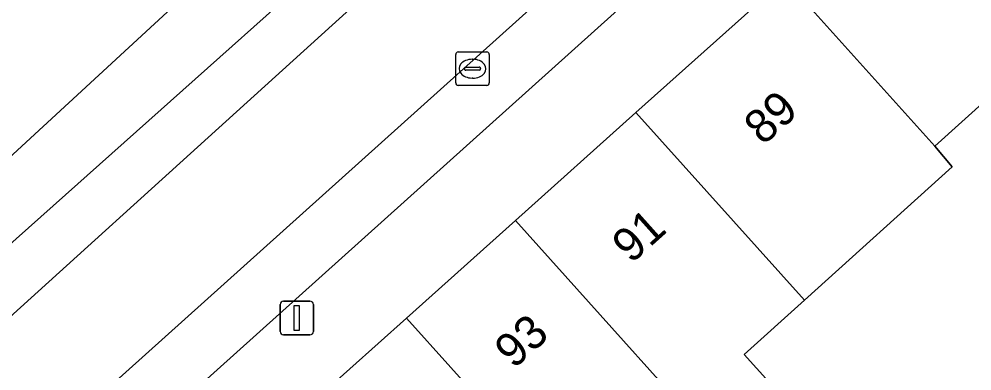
# Model space of a CAD drawing. Extents: x 162172 to 163187, y 382874 to 383685.
# Drawn here: x 162755.23 to 162783.66, y 383317.62 to 383328.11 of the extents above; entities that cross this region are included whole.
import ezdxf

# ---------------------------------------------------------------- set-up
doc = ezdxf.new("R2010")
doc.units = 0
for name, color, linetype in [('IMGEO_Berm_groen', 7, 'Continuous'), ('IMGEO_Erf', 7, 'Continuous'), ('IMGEO_Kolk', 7, 'Continuous'), ('IMGEO_Lichtmast', 7, 'Continuous'), ('IMGEO_Pand', 7, 'Continuous'), ('IMGEO_Pand_nummerreeks', 7, 'Continuous'), ('IMGEO_Parkeervlak_open', 7, 'Continuous'), ('IMGEO_Rijbaan_lokaal_open', 7, 'Continuous'), ('IMGEO_Voetpad_halfverhard', 7, 'Continuous'), ('IMGEO_Voetpad_open', 7, 'Continuous')]:
    doc.layers.add(name, color=color, linetype=linetype)

msp = doc.modelspace()

# ---------------------------------------------------------------- linework, layer by layer
at = {"layer": 'IMGEO_Berm_groen'}
for points in [[(162744.611, 383310), (162750.185, 383314.921), (162765.945, 383329.187), (162788.183, 383349.104), (162785.604, 383352.953), (162793.329, 383359.988), (162800.361, 383366.393), (162802.051, 383364.873), (162802.602, 383364.378)], [(162752.484, 383321.73), (162768.734, 383336.704)], [(162770.061, 383334.875), (162753.755, 383320.332)]]:
    msp.add_lwpolyline(points, dxfattribs=at)
at = {"layer": 'IMGEO_Erf'}
msp.add_lwpolyline([(162789.669, 383316.528), (162794.092, 383320.435), (162788.223, 383327.136), (162786.811, 383325.865), (162785.681, 383327.136), (162782.559, 383324.327), (162783.078, 383323.703), (162778.663, 383319.729), (162776.869, 383318.115), (162779.073, 383315.667)], dxfattribs=at)
at = {"layer": 'IMGEO_Kolk'}
for p, q in [((162768.26, 383326.208), (162768.26, 383327.06)), ((162768.335, 383327.134), (162769.187, 383327.134)), ((162769.261, 383327.06), (162769.261, 383326.208)), ((162768.748, 383326.914), (162768.773, 383326.914)), ((162768.519, 383326.628), (162768.519, 383326.64)), ((162768.957, 383326.591), (162768.559, 383326.591)), ((162768.562, 383326.677), (162768.96, 383326.677)), ((162769.003, 383326.64), (162769.003, 383326.628)), ((162768.771, 383326.354), (162768.746, 383326.354)), ((162769.187, 383326.134), (162768.335, 383326.134))]:
    msp.add_line(p, q, dxfattribs=at)
for points in [[(162768.26, 383326.208), (162768.26, 383327.06)], [(162768.335, 383327.134), (162769.187, 383327.134)], [(162769.261, 383327.06), (162769.261, 383326.208)], [(162769.187, 383326.134), (162768.335, 383326.134)]]:
    msp.add_lwpolyline(points, dxfattribs=at)
for centre, radius, start, end in [((162768.337, 383327.058), 0.0765, 91.552, 178.448), ((162768.337, 383327.058), 0.0765, 91.552, 178.448), ((162769.185, 383327.058), 0.0765, 1.552, 88.448), ((162769.185, 383327.058), 0.0765, 1.552, 88.448), ((162768.559, 383326.637), 0.0403, 85.8775, 175.7526), ((162768.556, 383326.627), 0.0366, 178.938, 274.7102), ((162768.96, 383326.634), 0.043, 264.8664, 352.4533), ((162768.964, 383326.639), 0.0386, 1.7309, 96.639), ((162768.337, 383326.21), 0.0765, 181.552, 268.448), ((162768.337, 383326.21), 0.0765, 181.552, 268.448), ((162769.185, 383326.21), 0.0765, 271.552, 358.448), ((162769.185, 383326.21), 0.0765, 271.552, 358.448)]:
    msp.add_arc(centre, radius, start, end, dxfattribs=at)
for centre, major_axis, ratio, start_param, end_param in [((162768.747, 383326.634), (-0.387, 0.002), 0.722429, 4.712389, 7.853982), ((162768.772, 383326.634), (-0.39, 0.002), 0.717154, 1.570796, 4.712389)]:
    msp.add_ellipse(centre, major_axis=major_axis, ratio=ratio, start_param=start_param, end_param=end_param, dxfattribs=at)
at = {"layer": 'IMGEO_Lichtmast'}
for p, q in [((162763.121, 383319.698), (162763.911, 383319.698)), ((162763.911, 383319.698), (162763.121, 383319.698)), ((162763.021, 383318.798), (162763.021, 383319.598)), ((162763.021, 383319.598), (162763.021, 383318.798)), ((162764.011, 383319.598), (162764.011, 383318.798)), ((162764.011, 383318.798), (162764.011, 383319.598)), ((162763.911, 383318.698), (162763.121, 383318.698)), ((162763.121, 383318.698), (162763.911, 383318.698))]:
    msp.add_line(p, q, dxfattribs=at)
msp.add_lwpolyline([(162763.441, 383319.573), (162763.591, 383319.573), (162763.591, 383318.823), (162763.441, 383318.823), (162763.441, 383319.573)], dxfattribs=at)
for centre, start, end in [((162763.121, 383319.598), 90, 180), ((162763.121, 383319.598), 90, 180), ((162763.911, 383319.598), 0, 90), ((162763.911, 383319.598), 360, 90), ((162763.121, 383318.798), 180, 270), ((162763.121, 383318.798), 180, 270), ((162763.911, 383318.798), 270, 0), ((162763.911, 383318.798), 270, 0)]:
    msp.add_arc(centre, 0.1, start, end, dxfattribs=at)
at = {"layer": 'IMGEO_Pand'}
for points in [[(162782.559, 383324.327), (162785.681, 383327.136), (162786.811, 383325.865), (162788.223, 383327.136), (162782.641, 383333.394), (162778.081, 383329.309)], [(162782.559, 383324.327), (162778.081, 383329.309), (162773.633, 383325.324), (162778.663, 383319.729), (162783.078, 383323.703)], [(162773.633, 383325.324), (162770.039, 383322.104), (162777.279, 383314.052), (162781.544, 383309.309), (162783.341, 383310.926), (162779.073, 383315.667), (162776.869, 383318.115), (162778.663, 383319.729)], [(162770.039, 383322.104), (162766.792, 383319.195), (162772.079, 383313.313), (162773.022, 383314.161), (162773.638, 383314.716), (162773.906, 383314.957), (162775.863, 383312.782), (162775.598, 383312.539), (162775.251, 383312.221), (162779.559, 383307.521), (162781.544, 383309.309), (162777.279, 383314.052)], [(162772.079, 383313.313), (162766.792, 383319.195), (162763.413, 383316.169), (162770.665, 383308.102), (162772.374, 383309.639), (162774.038, 383311.137)]]:
    msp.add_lwpolyline(points, close=True, dxfattribs=at)
at = {"layer": 'IMGEO_Parkeervlak_open'}
for points in [[(162843.693, 383394.145), (162811.886, 383365.593), (162808.297, 383362.372), (162752.534, 383312.314), (162752.272, 383312.079), (162752.63, 383312.208), (162753.767, 383312.366), (162754.785, 383312.353)], [(162755.461, 383312.558), (162842.607, 383390.811)]]:
    msp.add_lwpolyline(points, dxfattribs=at)
at = {"layer": 'IMGEO_Rijbaan_lokaal_open'}
msp.add_lwpolyline([(162752.534, 383312.314), (162808.297, 383362.372), (162805.798, 383364.945), (162788.183, 383349.104), (162765.945, 383329.187), (162750.185, 383314.921)], close=True, dxfattribs=at)
at = {"layer": 'IMGEO_Voetpad_halfverhard'}
for points in [[(162768.734, 383336.704), (162752.484, 383321.73)], [(162753.755, 383320.332), (162770.061, 383334.875)]]:
    msp.add_lwpolyline(points, dxfattribs=at)
at = {"layer": 'IMGEO_Voetpad_open'}
for points in [[(162842.607, 383390.811), (162755.461, 383312.558)], [(162763.413, 383316.169), (162766.792, 383319.195), (162770.039, 383322.104), (162773.633, 383325.324), (162778.081, 383329.309), (162782.641, 383333.394), (162783.75, 383334.333), (162788.4, 383338.504), (162792.867, 383342.51), (162796.664, 383345.915), (162801.13, 383349.921), (162805.597, 383353.928), (162810.063, 383357.934)]]:
    msp.add_lwpolyline(points, dxfattribs=at)

# ---------------------------------------------------------------- texts
at = {"layer": 'IMGEO_Pand_nummerreeks'}
for s, rotation, p in [('89', 41.8551, (162777.43, 383324.323)), ('91', 41.8546, (162773.493, 383320.795)), ('93', 41.8546, (162769.988, 383317.656))]:
    msp.add_text(s, height=1, rotation=rotation, dxfattribs=at).set_placement(p)

doc.saveas('drawing.dxf')
